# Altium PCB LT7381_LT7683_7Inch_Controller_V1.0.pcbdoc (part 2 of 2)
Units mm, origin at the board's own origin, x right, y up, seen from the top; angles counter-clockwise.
Board outline 88.99 x 77.25 mm, 2 copper layers (Top Layer, Bottom Layer); 119 components, 133 nets, 535 pads, 215 vias.
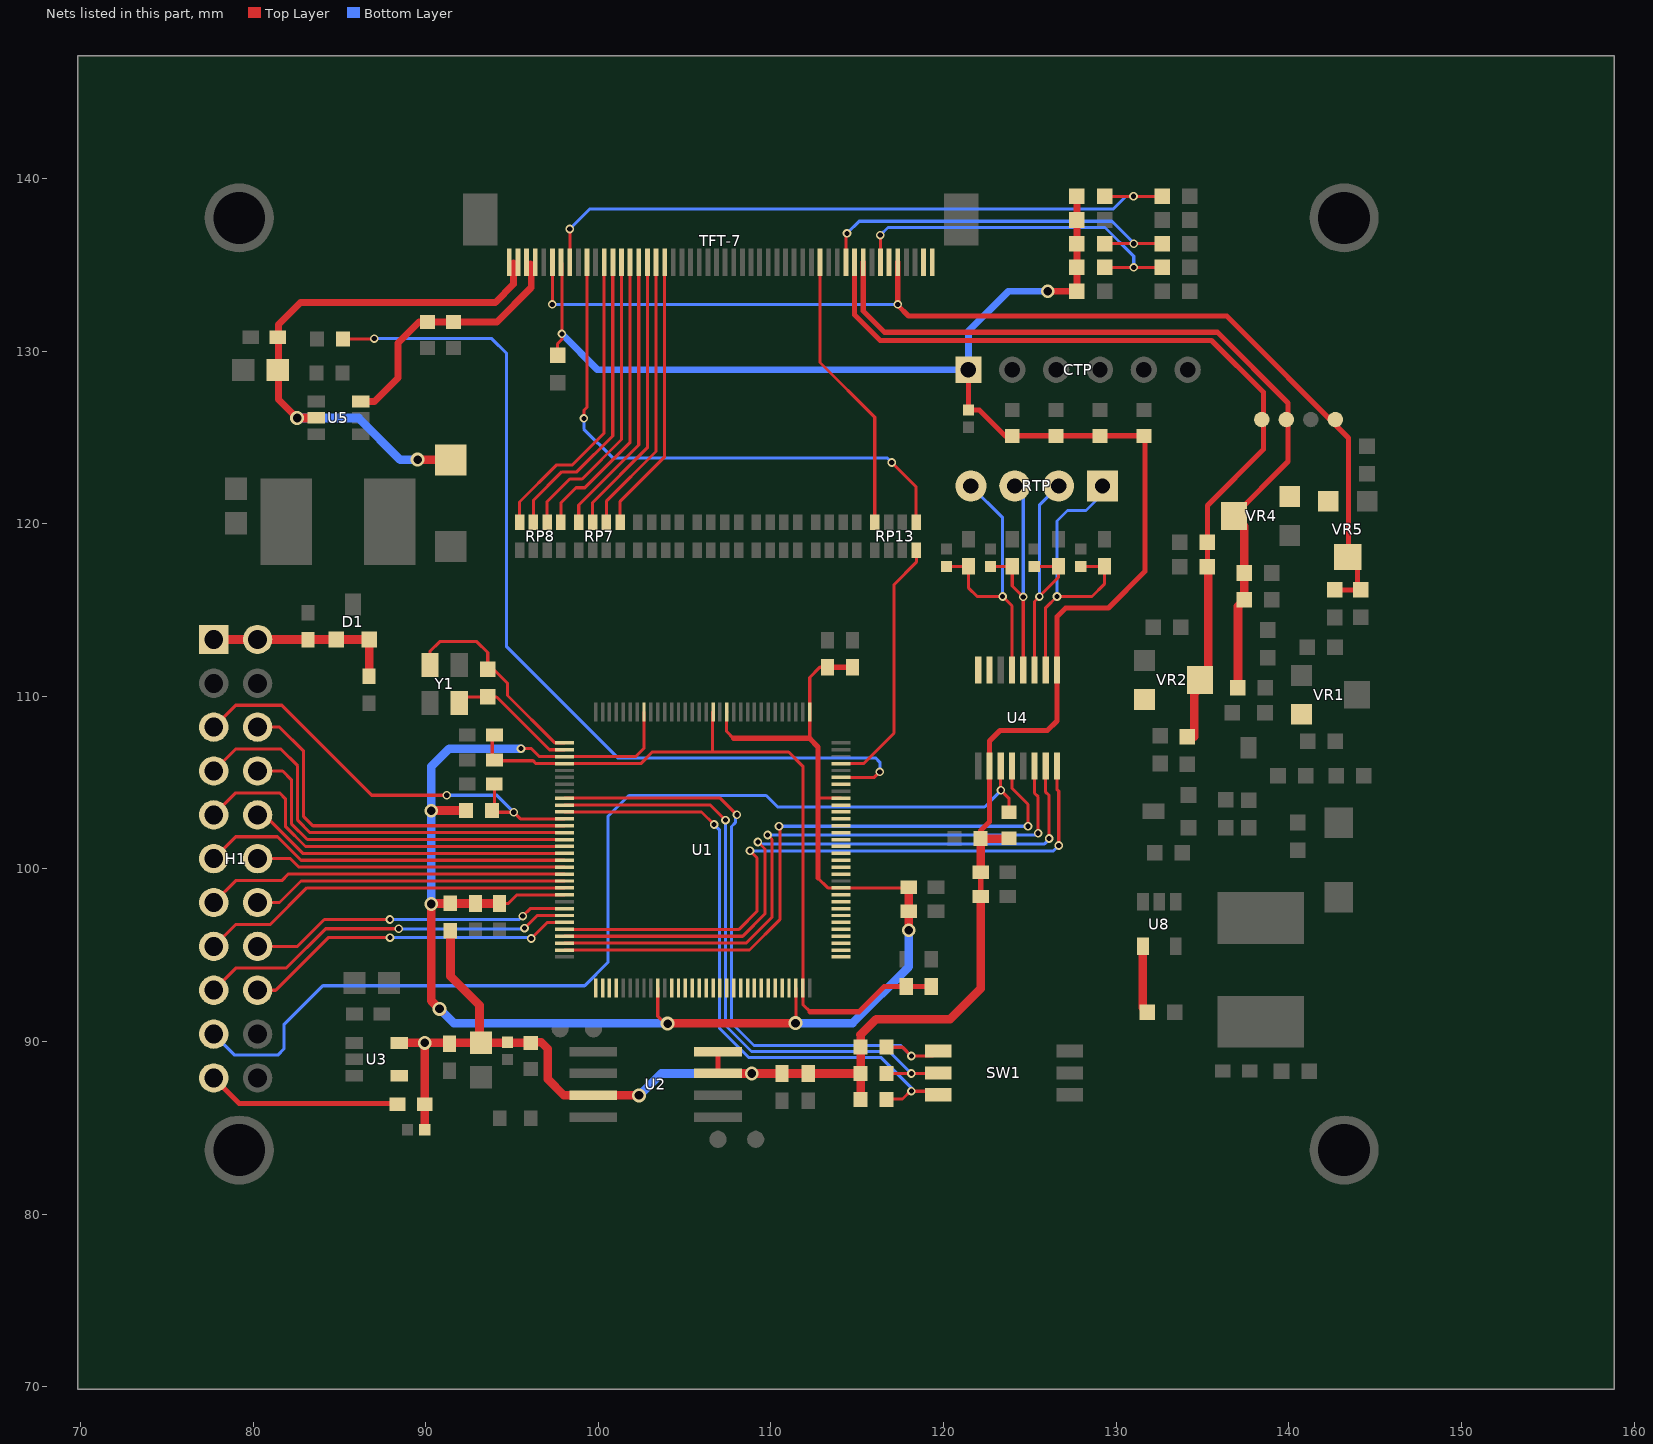
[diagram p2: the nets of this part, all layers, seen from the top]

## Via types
v1: diameter 0.8, hole 0.5, Top Layer to Bottom Layer, 151 vias
v2: diameter 0.5, hole 0.3, Top Layer to Bottom Layer, 64 vias

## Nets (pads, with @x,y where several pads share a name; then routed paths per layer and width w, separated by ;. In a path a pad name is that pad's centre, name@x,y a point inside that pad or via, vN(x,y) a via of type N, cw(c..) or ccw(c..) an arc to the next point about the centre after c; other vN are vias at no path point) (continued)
LCD_RST: C94.1 R90.2 TFT-7.44 | length 21.1
  Top Layer w0.18: v2(116.332,136.716) 116.344,136.704 TFT-7.44@116.344,135.141 ; R90.2@129.325,134.849 v2(131.016,134.849) C94.1@132.652,134.849
  Bottom Layer w0.18: v2(116.332,136.716) 116.776,137.16 129.35,137.16 131.016,135.494 v2(131.016,134.849)
LCD_VSYNC: RP13.4 U1.93 | length 15
  Top Layer w0.18: U1.93@114.045,106.104 115.357,106.104 117.125,107.872 117.125,116.472 118.425,117.772 118.425,118.461 RP13.4@118.412,118.475
LDO_CAP12: C10.1 C11.1 C14.1 C15.1 U1.4 U1.63 U1.111 | length 44.4
  Top Layer w0.18: C15.1@93.857,107.626 93.857,106.272 96.225,106.272 96.393,106.104 U1.4@98.045,106.104 102.457,106.104 103.125,106.772 106.625,106.772 ; U1.111@106.645,109.104 106.625,109.084 106.625,106.772 ; 112.268,91.729 111.845,92.152 U1.63@111.845,93.104 111.845,105.952 111.025,106.772 106.625,106.772
  Top Layer w0.3: 112.268,91.729 115.097,91.729 116.564,93.196 C10.1@117.835,93.196 C11.1@119.289,93.196
LEDA: C53.1 C55.1 D52.2 TFT-7.1 TFT-7.2 U5.5 | length 32.7
  Top Layer w0.4: v1(82.55,126.123) 81.483,127.19 81.483,131.534 82.753,132.804 94.031,132.804 95.098,133.871 95.098,135.09
  Top Layer w0.5: v1(82.55,126.123) 83.64,126.123 U5.5@83.65,126.133 ; v1(89.535,123.71) 91.423,123.71 D52.2@91.451,123.682
  Bottom Layer w0.5: v1(82.55,126.123) 86.106,126.123 88.519,123.71 v1(89.535,123.71)
LEDK: R53.1 R54.1 TFT-7.3 TFT-7.4 U5.3 | length 15.2
  Top Layer w0.4: U5.3@86.25,127.083 87.039,127.083 88.392,128.436 88.392,130.468 89.603,131.678 R54.1@90.098,131.678 R53.1@91.622,131.678 94.124,131.678 96.114,133.668 96.114,134.989 96.063,135.04
LT768_CS#: H1.6 U1.13 | length 22.4
  Top Layer w0.18: H1.6@80.264,108.216 81.534,108.216 82.931,106.819 82.931,103.034 83.464,102.501 98.042,102.501 U1.13@98.045,102.504
LT768_DB0: H1.11 U1.18 | length 21.4
  Top Layer w0.18: H1.11@77.724,100.596 78.994,101.866 81.419,101.866 82.781,100.504 U1.18@98.045,100.504
LT768_DB1: H1.12 U1.19 | length 18
  Top Layer w0.18: H1.12@80.264,100.596 82.169,100.596 82.661,100.104 U1.19@98.045,100.104
LT768_DB2: H1.13 U1.20 | length 21
  Top Layer w0.18: H1.13@77.724,98.056 78.994,99.326 81.661,99.326 82.042,99.707 98.042,99.707 U1.20@98.045,99.704
LT768_DB3: H1.14 U1.21 | length 18.3
  Top Layer w0.18: H1.14@80.264,98.056 81.534,98.056 82.782,99.304 U1.21@98.045,99.304
LT768_DB4_SCS#: H1.15 U1.22 | length 21.7
  Top Layer w0.18: H1.15@77.724,95.516 78.994,96.786 81.001,96.786 83.119,98.904 U1.22@98.045,98.904
LT768_DB5_SDO: H1.16 U1.25 | length 18.7
  Top Layer w0.18: H1.16@80.264,95.516 82.575,95.516 84.131,97.072 v2(87.925,97.072) ; v2(95.625,97.272) 96.057,97.704 U1.25@98.045,97.704
  Bottom Layer w0.18: v2(87.925,97.072) 95.425,97.072 v2(95.625,97.272)
LT768_DB6_SDI: H1.17 U1.26 | length 22.1
  Top Layer w0.18: H1.17@77.724,92.976 79.02,94.272 81.941,94.272 84.204,96.535 88.441,96.535 v2(88.443,96.533) ; v2(95.725,96.572) 96.457,97.304 U1.26@98.045,97.304
  Bottom Layer w0.18: v2(88.443,96.533) 95.686,96.533 v2(95.725,96.572)
LT768_DB7_SCLK: H1.18 U1.27 | length 19.5
  Top Layer w0.18: H1.18@80.264,92.976 81.305,92.976 84.355,96.025 v2(87.935,96.025) ; v2(96.114,95.974) 97.043,96.904 U1.27@98.045,96.904
  Bottom Layer w0.18: v2(87.935,96.025) 87.937,96.023 96.065,96.023 v2(96.114,95.974)
LT768_INT: U1.36
LT768_PS0: R3.1 SW1.6 U1.11 | length 36.9
  Top Layer w0.18: U1.11@98.045,103.304 105.979,103.304 v2(106.705,102.577) ; R3.1@116.704,86.645 116.731,86.672 117.623,86.672 v2@118.135,87.185 ; v2(118.135,87.134) 118.147,87.122 119.481,87.122 SW1.6@119.685,86.919
  Bottom Layer w0.18: v2(106.705,102.577) 107.01,102.272 107.01,90.792 108.727,89.075 116.398,89.075 118.135,87.337 v2(118.135,87.134)
LT768_PS1: R4.1 SW1.5 U1.10 | length 36.5
  Top Layer w0.18: U1.10@98.045,103.704 106.493,103.704 v2(107.366,102.831) ; R4.1@116.705,88.164 116.718,88.15 v2(118.135,88.15) 119.646,88.15 SW1.5@119.685,88.189
  Bottom Layer w0.18: v2(107.366,102.831) 107.366,90.932 108.872,89.425 116.86,89.425 v2(118.135,88.15)
LT768_PS2: R5.1 SW1.4 U1.9 | length 37.1
  Top Layer w0.18: U1.9@98.045,104.104 107.058,104.104 v2(108.026,103.136) ; R5.1@116.704,89.693 116.725,89.672 117.629,89.672 v2(118.135,89.166) 119.392,89.166 SW1.4@119.685,89.459
  Bottom Layer w0.18: v2(108.026,103.136) 107.938,103.048 107.938,102.682 107.716,102.46 107.716,91.077 109.018,89.776 117.526,89.776 v2(118.135,89.166)
LT768_PWM0: U1.90
LT768_PWM1: R51.1 U1.91 | length 54.2
  Top Layer w0.18: R51.1@85.208,130.695 86.994,130.695 v2(87.02,130.722) ; U1.91@114.045,105.304 115.985,105.304 v2(116.307,105.625)
  Bottom Layer w0.18: v2(87.02,130.722) 93.828,130.722 94.691,129.858 94.691,112.864 101.117,106.438 116.053,106.438 116.307,106.184 v2(116.307,105.625)
LT768_RD#: H1.7 U1.14 | length 24.7
  Top Layer w0.18: H1.7@77.724,105.676 78.994,106.946 81.61,106.946 82.58,105.976 82.58,102.826 83.303,102.104 U1.14@98.045,102.104
LT768_RS/A0: H1.9 U1.16 | length 23.1
  Top Layer w0.18: H1.9@77.724,103.136 78.994,104.406 81.534,104.406 81.87,104.07 81.87,102.47 83.036,101.304 U1.16@98.045,101.304
LT768_RST: C40.1 H1.5 R2.1 U1.12 | length 26.5
  Top Layer w0.18: H1.5@77.724,108.216 78.994,109.486 81.661,109.486 86.875,104.272 v2(91.225,104.272) ; R2.1@93.853,103.39 R2.1@93.958,103.285 ; C40.1@93.98,104.914 93.98,103.307 R2.1@93.958,103.285 ; U1.12@98.045,102.904 95.482,102.904 v2(95.101,103.285) R2.1@93.958,103.285
  Bottom Layer w0.18: v2(91.225,104.272) 94.114,104.272 v2(95.101,103.285)
LT768_VDD3.3V: C2.1 C3.1 C4.1 C5.1 C6.1 C7.1 L10.2 R2.2 U1.3 U1.23 U1.42 U1.62 U1.75 U1.88 U1.97 U1.109 U1.121 | length 104.9
  Top Layer w0.18: C7.1@94.382,98.002 94.789,98.002 95.29,98.504 U1.23@98.045,98.504 ; v2(95.525,106.972) 96.125,106.972 96.593,106.504 U1.3@98.045,106.504 102.157,106.504 102.645,106.992 U1.121@102.645,109.104 ; U1.42@103.445,93.104 103.445,91.461 103.861,91.046 v1(104.013,91.046) ; U1.109@107.445,109.104 107.425,109.084 107.425,107.972 107.825,107.572 ; v1@111.445,91.092 U1.62@111.445,93.104 ; 112.245,107.552 112.245,107.572 U1.97@112.245,109.104 112.245,111.092 112.835,111.682 C4.1@113.278,111.682 ; 112.725,99.472 113.293,98.904 U1.75@114.045,98.904 117.94,98.904 C3.1@117.981,98.944 ; 112.725,104.099 112.73,104.104 U1.88@114.045,104.104
  Top Layer w0.3: v1(90.325,97.972) v1@90.355,98.002 ; v1(90.325,103.372) v1@90.343,103.39 ; v1(104.013,91.046) v1@104.039,91.072 ; 107.825,107.572 112.245,107.572 ; 112.245,107.552 112.725,107.072 112.725,104.099 112.725,99.472 ; C4.1@113.278,111.682 C5.1@114.732,111.682
  Top Layer w0.5: v1(90.325,97.972) 90.325,92.372 v1@90.925,91.772 ; v1@90.343,103.39 R2.2@92.346,103.39 ; v1@90.355,98.002 L10.2@91.423,98.002 C6.1@92.883,98.002 C7.1@94.28,98.002 ; v1@104.039,91.072 v1(111.425,91.072) ; v1@117.981,96.472 C2.1@117.981,97.547 C3.1@117.981,98.944
  Bottom Layer w0.3: v1@103.987,91.072 v1(104.013,91.046)
  Bottom Layer w0.5: v1(90.325,97.972) v1(90.325,103.372) 90.325,105.934 91.363,106.972 v2(95.525,106.972) ; v1(90.799,91.898) 91.625,91.072 v1@103.987,91.072 ; v1(111.425,91.072) 114.725,91.072 117.981,94.328 v1@117.981,96.472
  other v1: 117.983,96.456
LT768_WAIT: H1.10 U1.17 | length 18.7
  Top Layer w0.18: H1.10@80.264,103.136 80.645,103.136 82.877,100.904 U1.17@98.045,100.904
LT768_WR#: H1.8 U1.15 | length 20.9
  Top Layer w0.18: H1.8@80.264,105.676 81.712,105.676 82.22,105.168 82.22,102.628 83.144,101.704 U1.15@98.045,101.704
LT768_XI: R1.1 U1.1 Y1.3 | length 12.2
  Top Layer w0.18: Y1.3@90.25,111.815 90.25,112.614 90.805,113.169 92.964,113.169 93.597,112.536 R1.1@93.597,111.565 93.933,111.565 94.742,110.756 94.742,110.046 97.484,107.304 U1.1@98.045,107.304
LT768_XO: R1.2 U1.2 Y1.1 | length 7.5
  Top Layer w0.18: Y1.1@91.95,109.615 92.3,109.965 R1.2@93.597,109.965 94.112,109.965 97.173,106.904 U1.2@98.045,106.904
MODE: R91.2 R92.1 TFT-7.8 | length 38.7
  Top Layer w0.18: TFT-7.8@98.344,135.141 98.349,135.146 v2(98.349,137.072) ; R91.2@129.325,138.964 v2(131.002,138.964) R92.1@132.652,138.964
  Bottom Layer w0.18: v2(98.349,137.072) 99.504,138.227 129.832,138.227 130.569,138.964 v2(131.002,138.964)
PCLK: RP13.8 TFT-7.37 | length 16.4
  Top Layer w0.18: TFT-7.37@112.844,135.141 112.844,129.333 116.012,126.165 RP13.8@116.012,120.075
R0: RP7.5 TFT-7.19 | length 16.1
  Top Layer w0.18: RP7.5@101.267,120.075 101.267,121.295 103.844,123.872 TFT-7.19@103.844,135.141
R1: RP7.6 TFT-7.18 | length 16.3
  Top Layer w0.18: RP7.6@100.467,120.075 100.482,120.09 100.482,121.324 103.344,124.185 TFT-7.18@103.344,135.141
R2: RP7.7 TFT-7.17 | length 16.4
  Top Layer w0.18: RP7.7@99.667,120.075 99.667,121.219 102.844,124.396 TFT-7.17@102.844,135.141
R3: RP7.8 TFT-7.16 | length 16.5
  Top Layer w0.18: RP7.8@98.867,120.075 98.867,121.08 102.344,124.556 TFT-7.16@102.344,135.141
R4: RP8.5 TFT-7.15 | length 17
  Top Layer w0.18: RP8.5@97.838,120.075 97.838,121.219 98.704,122.086 99.212,122.086 101.844,124.717 TFT-7.15@101.844,135.141
R5: RP8.6 TFT-7.14 | length 17.3
  Top Layer w0.18: RP8.6@97.038,120.075 97.038,121.283 98.349,122.594 99.06,122.594 101.344,124.877 TFT-7.14@101.344,135.141
R6: RP8.7 TFT-7.13 | length 17.5
  Top Layer w0.18: RP8.7@96.238,120.075 96.238,121.346 97.892,123 98.755,123 100.838,125.083 100.838,135.136 TFT-7.13@100.844,135.141
R7: RP8.8 TFT-7.12 | length 17.6
  Top Layer w0.18: RP8.8@95.438,120.075 95.438,121.257 97.587,123.406 98.501,123.406 100.33,125.235 100.33,135.128 TFT-7.12@100.344,135.141
RTP_CS: U1.29 U4.15 | length 37.8
  Top Layer w0.18: U1.29@98.045,96.104 108.357,96.104 109.652,97.399 109.652,101.155 v2(109.245,101.561) ; U4.15@125.914,105.974 125.914,104.451 126.111,104.254 v2(126.111,101.764)
  Bottom Layer w0.18: v2(109.245,101.561) 109.349,101.458 125.855,101.458 126.111,101.714 v2(126.111,101.764)
RTP_DCLK: U1.28 U4.16 | length 37.9
  Top Layer w0.18: U1.28@98.045,96.504 108.157,96.504 109.195,97.542 109.195,100.647 v2(108.788,101.053) ; U4.16@126.564,105.974 126.564,104.614 126.67,104.508 v2(126.67,101.358)
  Bottom Layer w0.18: v2(108.788,101.053) 108.991,101.053 108.993,101.051 126.363,101.051 v2(126.67,101.358)
RTP_DIN: U1.30 U4.14 | length 37.2
  Top Layer w0.18: U1.30@98.045,95.704 108.557,95.704 110.058,97.205 110.058,101.714 v2(109.804,101.968) ; U4.14@125.264,105.974 125.264,104.39 125.476,104.177 v2(125.476,102.07)
  Bottom Layer w0.18: v2(109.804,101.968) 109.806,101.966 125.371,101.966 v2(125.476,102.07)
RTP_INT: H1.19 R26.2 U4.11 | length 61.7
  Top Layer w0.18: U4.11@123.313,105.974 123.303,105.963 123.303,104.573 v2(123.317,104.558) 123.8,104.076 R26.2@123.8,103.285
  Bottom Layer w0.18: H1.19@77.724,90.436 78.942,89.218 81.432,89.218 81.788,89.574 81.788,90.982 84.043,93.237 99.205,93.237 100.554,94.585 100.554,103.042 101.771,104.26 109.723,104.26 110.39,103.592 122.375,103.592 123.317,104.534 v2(123.317,104.558)
RTP_SDO: U1.31 U4.12 | length 36.9
  Top Layer w0.18: U1.31@98.045,95.304 108.757,95.304 110.515,97.062 110.515,102.425 v2(110.465,102.476) ; U4.12@123.963,105.974 123.963,104.674 124.892,103.746 v2(124.892,102.476)
  Bottom Layer w0.18: v2(110.465,102.476) v2(124.892,102.476)
SHON: R80.2 U8.4 | length 3.9
  Top Layer w0.5: U8.4@131.545,95.512 131.545,91.963 R80.2@131.801,91.707
U/D: R95.2 R96.1 TFT-7.40 | length 22.5
  Top Layer w0.18: TFT-7.40@114.344,135.141 114.344,136.76 v2(114.402,136.818) ; R95.2@129.325,136.221 v2(131.01,136.221) R96.1@132.652,136.221
  Bottom Layer w0.18: v2(114.402,136.818) 115.105,137.521 129.751,137.521 131.01,136.262 v2(131.01,136.221)
VCOM: C83.1 pad.TP7@142.697,126.035 R83.2 TFT-7.6 TFT-7.46 VR5.2 | length 64.4
  Top Layer w0.18: v2(97.333,132.703) 97.344,132.714 TFT-7.6@97.344,135.141
  Top Layer w0.3: TFT-7.46@117.344,135.141 117.348,135.137 v2(117.348,132.703) 117.348,132.652 117.97,132.03 136.397,132.03 143.459,124.968 143.459,118.161 143.967,117.653 143.967,116.167 R83.2@142.85,116.167
  Bottom Layer w0.18: v2(97.333,132.703) v2(117.348,132.703)
VDD_3.3V: C1.1 C8.1 C9.1 C18.1 C28.1 C29.1 C93.1 CTP.1 ESD1.1 ESD2.1 ESD8.1 L2.1 L10.1 R3.2 R4.2 R5.2 R15.1 R16.1 R17.1 R18.1 R25.2 R26.1 R33.2 R90.1 R91.1 R93.1 R95.1 R97.1 TFT-7.7 U2.3 U2.7 U2.8 U3.5 U4.1 U4.10 | length 155.9
  Top Layer w0.18: C93.1@97.638,129.756 97.638,130.417 97.892,130.671 v2(97.892,130.996) 97.892,135.093 TFT-7.7@97.844,135.141 ; v1(102.357,86.885) v1@102.362,86.88 ; R26.1@123.782,101.761 R26.1@123.8,101.778
  Top Layer w0.2: L2.1@89.941,86.373 L2.1@89.951,86.364
  Top Layer w0.3: 92.38,89.852 92.38,89.926 ; 92.55,89.926 92.804,89.926 C18.1@92.885,90.007 ; U2.8@106.93,89.425 U2.7@106.93,88.155 U2.7@106.933,88.152 ; R4.2@115.187,88.152 R4.2@115.198,88.163 ; CTP.1@121.437,128.917 ESD8.1@121.437,126.59 122.063,126.59 123.562,125.09 R15.1@123.977,125.09 R17.1@129.057,125.09 R18.1@131.597,125.09 131.674,125.014 131.674,117.246 129.552,115.125 127.076,115.125 126.564,114.612 U4.1@126.564,111.534 126.568,111.53 126.568,108.572 126.009,108.013 123.266,108.013 122.664,107.41 U4.10@122.664,105.974 122.664,102.733 122.14,102.209 R25.2@122.14,101.761 R25.2@122.149,101.752 ; C8.1@122.149,98.412 C9.1@122.149,99.809
  Top Layer w0.4: v1(126.035,133.465) 127.712,133.465 R97.1@127.725,133.478 R90.1@127.725,134.849 R95.1@127.725,136.221 R93.1@127.725,137.593 R91.1@127.725,138.964
  Top Layer w0.5: U3.5@88.475,89.926 v1@89.941,89.926 ; L2.1@89.941,86.373 v1@89.941,89.926 ; ESD2.1@89.951,84.9 L2.1@89.951,86.364 ; L10.1@91.44,96.513 91.44,93.79 93.116,92.114 C18.1@93.116,89.926 ; 92.55,89.926 92.38,89.926 v1@89.941,89.926 ; C18.1@92.804,89.926 C18.1@93.116,89.926 ; v1(102.357,86.885) U2.3@99.707,86.885 98.012,86.885 97.079,87.818 97.079,89.574 96.68,89.972 96.034,89.972 95.988,89.926 C18.1@93.116,89.926 ; U2.7@106.933,88.152 v1(108.882,88.152) C28.1@110.637,88.152 C29.1@112.161,88.152 R4.2@115.187,88.152 ; 115.184,90.394 116.09,91.3 120.371,91.3 122.149,93.078 C8.1@122.149,98.412 ; R3.2@115.198,86.645 R4.2@115.198,88.152 ; R4.2@115.198,88.164 R5.2@115.198,89.693 115.198,90.394 ; R25.2@122.14,101.761 R26.1@123.782,101.761 ; C9.1@122.149,99.809 R25.2@122.149,101.752
  Bottom Layer w0.3: v1(102.357,86.885) v1@102.357,86.901 ; v1@108.88,88.15 v1(108.882,88.152)
  Bottom Layer w0.4: v2(97.892,130.996) 97.892,130.976 99.95,128.917 CTP.1@121.437,128.917 121.437,131.153 123.749,133.465 v1(126.035,133.465)
  Bottom Layer w0.5: v1@102.357,86.901 102.395,86.901 103.644,88.15 v1@108.88,88.15
  other v1: 89.941,89.928
VDD_3.3V_O: H1.21 L2.2 | length 11.3
  Top Layer w0.3: H1.21@77.724,87.896 79.196,86.424 88.316,86.424 L2.2@88.367,86.373
VGH: C87.1 C88.1 pad.TP11 R86.1 TFT-7.41 VR2.2 | length 50.3
  Top Layer w0.3: TFT-7.41@114.844,135.141 114.844,132.108 116.332,130.62 135.521,130.62 138.532,127.61 138.532,124.308 135.28,121.056 C87.1@135.28,118.923 135.28,117.514 C88.1@135.267,117.501
  Top Layer w0.5: R86.1@134.518,107.658 134.518,110.185 135.331,110.998 135.331,117.436 C88.1@135.267,117.501
VGL: C91.1 C92.1 pad.TP10 R88.2 TFT-7.42 VR4.2 | length 48
  Top Layer w0.3: TFT-7.42@115.344,135.141 115.344,132.32 116.573,131.09 135.864,131.09 139.954,127 139.954,123.596 136.817,120.459 VR4.2@136.817,120.447
  Top Layer w0.5: VR4.2@136.817,120.447 137.414,119.85 137.414,117.006 C92.1@137.414,115.583 137.051,115.221 R88.2@137.051,110.343
VIN: D1.1 D1.2 H1.1 H1.2 L1.1 L50.1 | length 11.1
  Top Layer w0.5: H1.1@77.724,113.296 H1.2@80.264,113.296 84.826,113.296 D1.2@86.73,113.296 ; L1.1@86.716,111.164 86.731,111.179 D1.2@86.731,113.295
VSYNC: RP13.5 TFT-7.10 | length 32.4
  Top Layer w0.18: v2(99.162,126.099) 99.162,126.556 99.344,126.738 TFT-7.10@99.344,135.141 ; v2(116.992,123.546) 118.412,122.126 RP13.5@118.412,120.075
  Bottom Layer w0.18: v2(99.162,126.099) 99.162,125.479 100.828,123.813 116.725,123.813 v2(116.992,123.546)
X+: C33.1 ESD4.1 RTP.1 U4.2 | length 18.1
  Top Layer w0.18: U4.2@125.914,111.534 125.914,115.131 v2(126.568,115.785) 128.6,115.785 129.311,116.496 129.311,117.525 C33.1@129.314,117.528 ESD4.1@127.94,117.528
  Bottom Layer w0.18: v2(126.568,115.785) 126.568,120.154 127.178,120.764 128.245,120.764 129.203,121.722 RTP.1@129.203,122.186
X-: C35.1 ESD6.1 RTP.3 U4.4 | length 14.2
  Top Layer w0.18: ESD6.1@122.71,117.528 C35.1@123.98,117.528 123.977,117.525 123.977,116.395 v2(124.614,115.758) U4.4@124.614,111.534
  Bottom Layer w0.18: RTP.3@124.123,122.186 124.614,121.695 v2(124.614,115.758)
Y+: C34.1 ESD5.1 RTP.2 U4.3 | length 14.8
  Top Layer w0.18: ESD5.1@125.25,117.528 C34.1@126.647,117.528 126.647,116.88 v2(125.546,115.779) 125.264,115.497 U4.3@125.264,111.534
  Bottom Layer w0.18: v2(125.546,115.779) 125.546,121.07 RTP.2@126.663,122.186
Y-: C65.1 ESD7.1 RTP.4 U4.5 | length 16.3
  Top Layer w0.18: ESD7.1@120.17,117.528 C65.1@121.44,117.528 121.44,116.942 121.437,116.94 121.437,116.293 121.945,115.785 v2(123.419,115.785) 123.963,115.24 U4.5@123.963,111.534
  Bottom Layer w0.18: RTP.4@121.583,122.186 123.419,120.35 v2(123.419,115.785)
"": TFT-7.45 TFT-7.49 TFT-7.50 U1.33 U1.34 U1.35 U1.44 U1.45 U1.46 U1.47 U1.48 U1.49 U1.50 U1.51 U1.52 U1.53 U1.54 U1.55 U1.56 U1.57 U1.58 U1.59 U1.60 U1.61 U1.65 U1.66 U1.67 U1.68 U1.69 U1.70 U1.71 U1.72 U1.73 U1.74 U1.77 U1.78 U1.79 U1.80 U1.81 U1.82 U1.83 U1.84 U1.85 U1.86 U1.87 U3.4 U4.7 U4.8 VR1.1 VR2.1 VR4.1 VR5.1

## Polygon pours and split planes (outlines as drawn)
GND on Bottom Layer (solid, remove dead copper, pour order 0): 76.2,116.752 92.304,116.752 93.472,117.92 93.472,133.16 92.151,134.481 76.2,134.481
GND on Top Layer (solid, remove dead copper, pour order 1): 76.2,80.716 76.2,116.447 92.456,116.447 93.777,117.768 93.777,133.262 92.253,134.786 76.2,134.786 76.2,140.729 146.187,140.729 146.2,140.716 146.2,126.812 137.347,126.812 131.826,121.258 131.826,117.209 129.438,114.821 129.438,88.304 131.47,86.272 146.202,86.272 146.202,80.718 146.2,80.716
GND on Top Layer (solid, remove dead copper, pour order 2): 146.202,86.576 131.623,86.576 129.794,88.405 129.794,114.618 132.131,116.955 132.131,121.12 137.516,126.505 146.202,126.505
GND on Bottom Layer (solid, remove dead copper, pour order 3): 76.2,80.716 76.2,116.447 92.456,116.447 93.777,117.768 93.777,133.262 92.253,134.786 76.2,134.786 76.2,140.729 146.187,140.729 146.2,140.716 146.2,126.812 137.349,126.812 131.826,121.256 131.826,117.209 129.438,114.821 129.438,88.304 131.47,86.272 146.202,86.272 146.202,80.718 146.2,80.716
GND on Bottom Layer (solid, remove dead copper, pour order 4): 146.202,86.576 131.623,86.576 129.794,88.405 129.794,114.618 132.131,116.955 132.131,121.12 137.516,126.505 146.202,126.505
GND on Top Layer (solid, remove dead copper, pour order 5): 76.2,116.752 92.304,116.752 93.472,117.92 93.472,133.16 92.151,134.481 76.2,134.481

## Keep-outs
Board Outline Layer:
  lines w0.254 net "": 76.2,83.116 ccw(c78.6,83.116) 78.6,80.716 143.8,80.716 ccw(c143.8,83.116) 146.2,83.116 146.2,138.316 ccw(c143.8,138.316) 143.8,140.716 78.6,140.716 ccw(c78.6,138.316) 76.2,138.316 76.2,83.116

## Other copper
Top Layer:
  drawing of 436 lines, arcs and shapes, not listed
Bottom Layer:
  region net Y-: 121.526,121.288 122.474,121.168 122.601,121.295 122.481,122.243
  region net X-: 123.882,121.319 124.524,120.837 124.704,120.954 125.013,122.056
  region net Y+: 125.764,122.243 125.644,121.295 125.772,121.168 126.719,121.288
  region net X+: 128.545,121.191 128.799,121.191 129.086,121.286 128.449,121.286
  region net RTP_INT: 77.671,89.588 78.562,89.471 78.689,89.598 78.572,90.489
  region net CTP_INT: 81.02,90.047 81.42,90.982 81.348,91.165 80.556,91.234
  region net CTP_SCL: 131.026,128.413 131.507,127.774 131.687,127.774 132.169,128.413
  region net CTP_SDA: 128.486,128.413 128.967,127.774 129.147,127.774 129.629,128.413
  region net CTP_RST: 125.946,128.413 126.427,127.774 126.607,127.774 127.089,128.413
  region net CTP_INT: 123.406,128.413 123.887,127.801 124.067,127.801 124.549,128.413
  region net VDD_3.3V: 120.375,129.117 120.375,128.717 120.675,128.417 120.675,129.417
  region net VDD_3.3V: 121.237,129.979 120.937,129.679 121.937,129.679 121.637,129.979
  region net FLASH_SPI_SO: 101.765,87.963 101.975,88.06 101.975,88.24 101.765,88.338
  region net FLASH_SPI_SCLK: 103.924,86.693 104.134,86.79 104.134,86.97 103.924,87.068
  region net FLASH_SPI_SCLK: 104.864,87.068 104.654,86.97 104.654,86.79 104.864,86.693
  region net FLASH_SPI_SO: 103.128,88.928 103.049,88.71 103.176,88.583 103.394,88.663
  region net LEDA: 82.815,125.823 83.15,125.873 83.15,126.373 82.815,126.423
  region net LEDA: 89.27,124.01 88.935,123.96 88.935,123.46 89.27,123.41
  region net LT768_RST: 95.117,103.535 94.899,103.614 94.772,103.487 94.851,103.269
  region net LT768_RST: 91.39,104.084 91.6,104.182 91.6,104.362 91.39,104.459
  region net +5V: 86.316,108.46 86.125,108.183 86.51,107.861 86.776,108.076
  region net +5V: 86.206,95.197 86.175,95.539 85.675,95.602 85.611,95.272
  region net LT768_DB7_SCLK: 95.988,96.191 95.759,96.113 95.723,95.933 95.915,95.823
  region net LT768_DB6_SDI: 95.533,96.732 95.337,96.623 95.366,96.443 95.591,96.361
  region net LT768_DB5_SDO: 95.376,97.288 95.361,97.136 95.489,97.008 95.641,97.022
  region net LT768_DB5_SDO: 88.09,96.884 88.3,96.982 88.3,97.162 88.09,97.259
  region net LT768_DB6_SDI: 88.608,96.346 88.818,96.443 88.818,96.623 88.608,96.721
  region net LT768_DB7_SCLK: 88.099,95.836 88.309,95.933 88.311,96.113 88.102,96.211
  region net RTP_SDO: 110.63,102.288 110.84,102.386 110.84,102.566 110.63,102.663
  region net RTP_DIN: 109.968,101.779 110.178,101.876 110.18,102.056 109.971,102.154
  region net RTP_CS: 109.318,101.322 109.569,101.368 109.651,101.548 109.474,101.663
  region net Y-: 123.606,115.951 123.509,116.16 123.329,116.16 123.231,115.951
  region net X-: 124.801,115.924 124.704,116.133 124.524,116.133 124.426,115.924
  region net Y+: 125.733,115.944 125.636,116.154 125.456,116.154 125.358,115.944
  region net X+: 126.756,115.951 126.658,116.16 126.478,116.16 126.381,115.951
  region net CTP_SDA: 99.8,111.272 100.015,111.365 100.023,111.545 99.818,111.647
  region net LT768_PWM1: 116.494,105.791 116.397,106 116.217,106 116.119,105.791
  region net LT768_PS2: 107.793,103.047 107.848,102.802 108.028,102.735 108.144,102.915
  region net LT768_PS0: 106.69,102.328 106.907,102.248 107.034,102.376 106.955,102.593
  region net RTP_SDO: 124.726,102.663 124.517,102.566 124.517,102.386 124.726,102.288
  region net RTP_DIN: 125.247,102.171 125.07,102.056 125.153,101.876 125.404,101.831
  region net RTP_CS: 125.862,101.744 125.799,101.529 125.945,101.42 126.162,101.52
  region net RTP_DCLK: 126.42,101.374 126.341,101.156 126.468,101.029 126.685,101.109
  region net LT768_PWM1: 87.186,130.534 87.395,130.632 87.395,130.812 87.186,130.909
  region net RTP_INT: 123.067,104.557 122.996,104.341 123.132,104.222 123.35,104.311
  region net CTP_RST: 111.163,103.915 111.373,104.012 111.373,104.192 111.163,104.29
  region net CTP_SCL: 120.208,114.106 120.002,114.174 119.875,114.046 119.943,113.84
  region net +5V: 84.001,87.762 84.051,87.426 84.551,87.426 84.601,87.762
  region net $1N79048: 131.845,99.619 131.695,99.955 131.395,99.955 131.245,99.619
  region net CTP_SDA: 118.046,111.643 117.837,111.545 117.837,111.365 118.046,111.268
  region net CTP_SDA: 119.923,111.634 119.826,111.843 119.646,111.843 119.548,111.634
  region net +5V: 134.371,88.039 134.421,87.704 134.921,87.704 134.971,88.039
  region net DE: 116.867,123.085 116.651,123.201 116.491,123.107 116.544,122.895
  region net HSYNC: 117.79,122.251 117.692,122.461 117.512,122.461 117.414,122.251
  region net VSYNC: 117.008,123.795 116.791,123.874 116.664,123.747 116.743,123.53
  region net HSYNC: 99.615,125.396 99.814,125.218 100.031,125.255 99.984,125.46
  region net VSYNC: 98.974,125.933 99.072,125.724 99.252,125.724 99.349,125.933
  region net DE: 98.432,125.524 98.642,125.377 98.828,125.445 98.785,125.652
  region net VDD_3.3V: 125.77,133.765 125.435,133.665 125.435,133.265 125.77,133.165
  region net MODE: 130.837,139.152 130.627,139.054 130.627,138.874 130.837,138.777
  region net L/R: 130.829,137.78 130.619,137.683 130.619,137.503 130.829,137.405
  region net U/D: 131.055,136.467 130.837,136.562 130.695,136.45 130.761,136.234
  region net LCD_RST: 131.203,135.015 131.106,135.224 130.926,135.224 130.828,135.015
  region net DITH: 131.048,133.727 130.831,133.807 130.703,133.679 130.783,133.462
  region net MODE: 98.598,137.056 98.678,137.273 98.55,137.4 98.333,137.321
  region net LCD_RST: 116.582,136.7 116.661,136.918 116.534,137.045 116.316,136.966
  region net U/D: 114.651,136.802 114.73,137.019 114.603,137.146 114.386,137.067
  region net L/R: 114.041,137.244 114.104,137.459 113.958,137.568 113.741,137.469
  region net DITH: 118.099,136.557 118.277,136.669 118.149,136.849 117.882,136.863
  region net VCOM: 117.183,132.89 116.973,132.793 116.973,132.613 117.183,132.515
  region net VCOM: 97.498,132.515 97.708,132.613 97.708,132.793 97.498,132.89
  region net $1N79048: 140.807,106.739 140.472,106.589 140.472,106.289 140.807,106.139

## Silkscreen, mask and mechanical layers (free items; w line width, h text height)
Top Silkscreen Layer:
  lines w0.1 net "": 120.625,92.11 129.946,92.11 129.946,96.428 120.625,96.428 120.625,92.11
  text "VCOM" at 142.348,130.821 h0.91 r270
  text "AVDD" at 140.831,130.701 h0.91 r270
  text "VGH" at 137.798,129.75 h0.91 r270
  text "VGL" at 139.315,129.668 h0.91 r270
  text "8080" at 122.403,95.277 h1
  text "6800" at 124.943,95.277 h1
  text "4-SPI" at 127.432,95.277 h1
  text "PS2" at 120.879,94.261 h1
  text "0" at 123.012,94.261 h1
  text "0" at 125.552,94.261 h1
  text "1" at 128.245,94.261 h1
  text "PS1" at 120.879,93.194 h1
  text "0" at 123.012,93.194 h1
  text "1" at 125.552,93.194 h1
  text "0" at 128.245,93.194 h1
  text "X" at 122.961,92.178 h1
  text "X" at 125.501,92.178 h1
  text "1" at 128.245,92.178 h1
  text "PS0" at 120.879,92.127 h1
  text "." at 151.994,76.42 h0.65
Bottom Silkscreen Layer:
  lines w0.2 net "": 88.129,86.424 88.138,86.433 88.138,114.77 ; 81.788,86.391 94.779,86.391 94.779,114.796 81.788,114.796 81.788,86.391 ; 120.498,123.914 135.763,123.914 135.763,127.444 120.498,127.444 120.498,123.914 ; 120.688,117.528 130.828,117.528 130.828,120.612 120.688,120.612 120.688,117.528
  text "LT7381/LT7683_7Inch_Controller V1.0" at 125.313,134.666 h2.38
  text "Levetop Semiconductor." at 125.236,131.567 h2.38
  text "INT" at 123.318,125.041 h0.84 r270
  text "SCL" at 130.968,124.561 h0.84 r270
  text "RST" at 125.868,124.526 h0.84 r270
  text "GND" at 133.519,124.488 h0.84 r270
  text "3V3" at 120.768,124.452 h0.84 r270
  text "SDA" at 128.418,124.452 h0.84 r270
  text "X-" at 125.242,118.676 h0.84
  text "X+" at 130.322,118.676 h0.84
  text "Y-" at 122.738,118.64 h0.84
  text "Y+" at 127.818,118.64 h0.84
  text "+5V" at 86.034,112.824 h0.84
  text "+5V" at 92.701,112.824 h0.84
  text "GND" at 85.943,110.382 h0.84
  text "GND" at 92.61,110.382 h0.84
  text "CS#" at 92.638,107.985 h0.84
  text "RST" at 85.983,107.832 h0.84
  text "RD#" at 86.034,105.191 h0.84
  text "WR#" at 92.79,105.191 h0.84
  text "RS" at 85.554,102.441 h0.84
  text "WAIT" at 92.85,102.441 h0.84
  text "DB0" at 85.923,99.955 h0.84
  text "DB1" at 92.426,99.955 h0.84
  text "DB2" at 85.923,97.469 h0.84
  text "DB3" at 92.74,97.469 h0.84
  text "DB4/SCS" at 87.513,95.095 h0.84
  text "DB5/SDO" at 94.18,95.095 h0.84
  text "DB6/SDI" at 87.199,92.504 h0.84
  text "DB7/SCK" at 94.162,92.504 h0.84
  text "RTP-INT" at 87.218,90.011 h0.84
  text "CTP-INT" at 93.903,90.011 h0.84
  text "3V3" at 85.96,87.525 h0.84
  text "GND" at 92.61,87.525 h0.84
